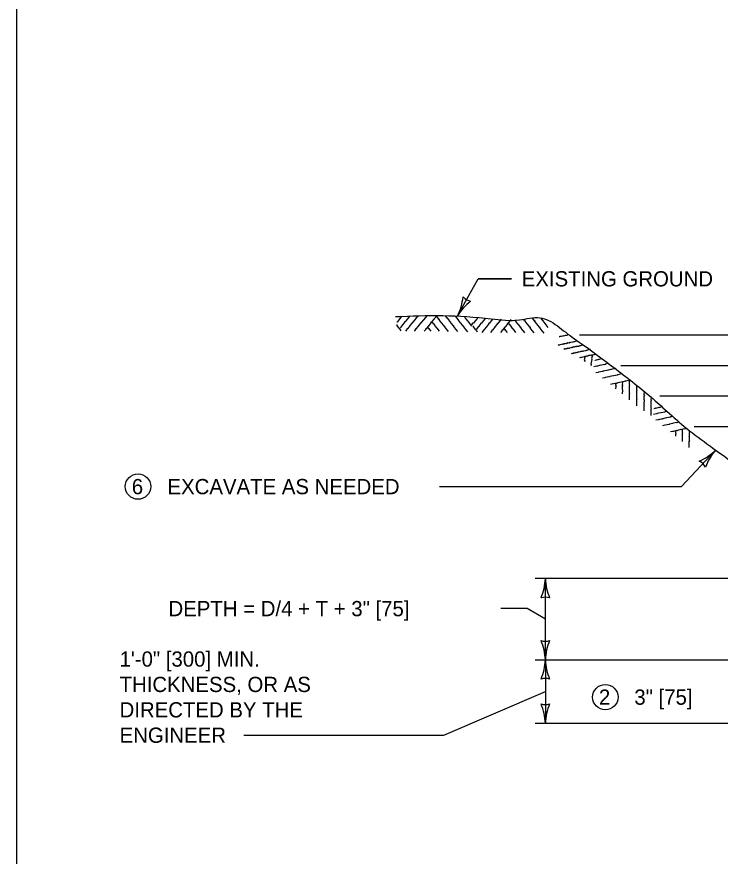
# Model space of a CAD drawing. Extents: x 49991.4 to 50021, y 49987.6 to 50011.4.
# Drawn here: x 49999.384 to 50002.154, y 49992.388 to 49995.693 of the extents above; entities that cross this region are included whole.
import ezdxf

# ---------------------------------------------------------------- set-up
doc = ezdxf.new("R2010")
doc.units = 0
for name, color, linetype in [('Level 1', 7, 'Continuous'), ('Level 2', 7, 'Continuous'), ('Level 3', 7, 'Continuous')]:
    doc.layers.add(name, color=color, linetype=linetype)

msp = doc.modelspace()

# ---------------------------------------------------------------- linework, layer by layer
at = {"layer": 'Level 1'}
for p, q in [((50001.5996, 49994.4405), (50003.795, 49994.4405)), ((50001.7626, 49994.3205), (50003.795, 49994.3205)), ((50001.9159, 49994.2005), (50003.1608, 49994.2005)), ((50002.052, 49994.0805), (50003.0002, 49994.0805))]:
    msp.add_line(p, q, dxfattribs=at)
msp.add_lwpolyline([(49999.3835, 49998.9992), (50016.7501, 49998.9992), (50016.7501, 49987.7988), (49999.3835, 49987.7988)], close=True, dxfattribs=at)
for points in [[(50000.8988, 49994.5131), (50000.8906, 49994.5035), (50000.8914, 49994.5019), (50000.8898, 49994.5019), (50000.8813, 49994.4914), (50000.8802, 49994.4915)], [(50000.932, 49994.5158), (50000.922, 49994.5042), (50000.9228, 49994.5026), (50000.9212, 49994.5026), (50000.9127, 49994.4921), (50000.9106, 49994.4922), (50000.9108, 49994.4901), (50000.902, 49994.4796), (50000.902, 49994.4775), (50000.9001, 49994.4769), (50000.8932, 49994.4682)], [(50000.9648, 49994.517), (50000.9521, 49994.5022), (50000.9529, 49994.5006), (50000.9513, 49994.5006), (50000.9428, 49994.4902), (50000.9406, 49994.4902), (50000.9409, 49994.4882), (50000.9321, 49994.4776), (50000.9321, 49994.4755), (50000.9302, 49994.4749), (50000.9218, 49994.4644), (50000.9198, 49994.4643), (50000.9202, 49994.4623), (50000.9141, 49994.4552)], [(50000.9985, 49994.5164), (50000.9862, 49994.5019), (50000.9869, 49994.5003), (50000.9853, 49994.5004), (50000.9768, 49994.4899), (50000.9747, 49994.4899), (50000.9749, 49994.4879), (50000.9661, 49994.4773), (50000.9661, 49994.4753), (50000.9642, 49994.4746), (50000.9559, 49994.4642), (50000.9539, 49994.464), (50000.9542, 49994.462), (50000.9482, 49994.4549)], [(50001.0388, 49994.5172), (50001.0261, 49994.5024), (50001.0268, 49994.5007), (50001.0252, 49994.5008), (50001.0167, 49994.4903), (50001.0146, 49994.4903), (50001.0148, 49994.4883), (50001.0061, 49994.4777), (50001.006, 49994.4757), (50001.0041, 49994.475), (50000.9958, 49994.4646), (50000.9937, 49994.4645), (50000.9941, 49994.4624), (50000.9881, 49994.4553)], [(50001.0839, 49994.4537), (50001.0786, 49994.461), (50001.0769, 49994.4606), (50001.0773, 49994.4621), (50001.069, 49994.4728), (50001.0695, 49994.4748), (50001.0675, 49994.4751), (50001.0591, 49994.486), (50001.0572, 49994.4865), (50001.057, 49994.4885), (50001.0487, 49994.499), (50001.049, 49994.501), (50001.047, 49994.5011), (50001.0375, 49994.5137)], [(50001.1207, 49994.4538), (50001.1145, 49994.4621), (50001.1128, 49994.4617), (50001.1132, 49994.4633), (50001.1049, 49994.4739), (50001.1054, 49994.476), (50001.1034, 49994.4762), (50001.095, 49994.4872), (50001.0931, 49994.4877), (50001.0929, 49994.4896), (50001.0846, 49994.5002), (50001.0849, 49994.5022), (50001.0829, 49994.5023), (50001.0725, 49994.5161)], [(50001.1596, 49994.4524), (50001.1534, 49994.4607), (50001.1517, 49994.4603), (50001.1521, 49994.4618), (50001.1438, 49994.4725), (50001.1443, 49994.4746), (50001.1423, 49994.4748), (50001.134, 49994.4857), (50001.132, 49994.4862), (50001.1318, 49994.4882), (50001.1235, 49994.4987), (50001.1238, 49994.5007), (50001.1218, 49994.5008), (50001.1126, 49994.5131)], [(50001.1759, 49994.4751), (50001.1681, 49994.4853), (50001.1662, 49994.4858), (50001.166, 49994.4878), (50001.1577, 49994.4983), (50001.158, 49994.5003), (50001.1559, 49994.5004), (50001.1482, 49994.5108)], [(50001.1983, 49994.5066), (50001.1915, 49994.4986), (50001.1923, 49994.497), (50001.1906, 49994.497), (50001.1822, 49994.4865), (50001.181, 49994.4866)], [(50001.2282, 49994.5055), (50001.2229, 49994.4993), (50001.2237, 49994.4977), (50001.2221, 49994.4977), (50001.2136, 49994.4872), (50001.2114, 49994.4873), (50001.2117, 49994.4852), (50001.2029, 49994.4747), (50001.2029, 49994.4726), (50001.201, 49994.472), (50001.1941, 49994.4633)], [(50001.2577, 49994.5028), (50001.253, 49994.4973), (50001.2538, 49994.4957), (50001.2522, 49994.4957), (50001.2437, 49994.4853), (50001.2415, 49994.4853), (50001.2418, 49994.4833), (50001.233, 49994.4727), (50001.233, 49994.4706), (50001.2311, 49994.47), (50001.2227, 49994.4595), (50001.2207, 49994.4594), (50001.221, 49994.4574), (50001.215, 49994.4503)], [(50001.2919, 49994.5027), (50001.287, 49994.497), (50001.2878, 49994.4954), (50001.2862, 49994.4955), (50001.2777, 49994.485), (50001.2756, 49994.485), (50001.2758, 49994.483), (50001.267, 49994.4724), (50001.267, 49994.4704), (50001.2651, 49994.4697), (50001.2568, 49994.4593), (50001.2547, 49994.4592), (50001.2551, 49994.4571), (50001.2491, 49994.45)], [(50001.3299, 49994.5009), (50001.327, 49994.4975), (50001.3277, 49994.4958), (50001.3261, 49994.4959), (50001.3176, 49994.4854), (50001.3155, 49994.4854), (50001.3157, 49994.4834), (50001.3069, 49994.4728), (50001.3069, 49994.4708), (50001.305, 49994.4701), (50001.2967, 49994.4597), (50001.2946, 49994.4596), (50001.295, 49994.4575), (50001.289, 49994.4504)], [(50001.3848, 49994.4488), (50001.3795, 49994.4561), (50001.3778, 49994.4557), (50001.3782, 49994.4572), (50001.3699, 49994.4679), (50001.3704, 49994.47), (50001.3684, 49994.4702), (50001.36, 49994.4811), (50001.3581, 49994.4816), (50001.3579, 49994.4836), (50001.3496, 49994.4941), (50001.3499, 49994.4961), (50001.3478, 49994.4962), (50001.3447, 49994.5004)], [(50001.4215, 49994.4489), (50001.4154, 49994.4572), (50001.4137, 49994.4568), (50001.4141, 49994.4584), (50001.4058, 49994.469), (50001.4063, 49994.4711), (50001.4043, 49994.4713), (50001.3959, 49994.4823), (50001.394, 49994.4828), (50001.3938, 49994.4847), (50001.3855, 49994.4953), (50001.3858, 49994.4973), (50001.3837, 49994.4974), (50001.3812, 49994.5008)], [(50001.4604, 49994.4475), (50001.4543, 49994.4558), (50001.4526, 49994.4554), (50001.453, 49994.4569), (50001.4447, 49994.4676), (50001.4452, 49994.4697), (50001.4432, 49994.4699), (50001.4348, 49994.4808), (50001.4329, 49994.4813), (50001.4327, 49994.4833), (50001.4244, 49994.4938), (50001.4247, 49994.4958), (50001.4227, 49994.4959), (50001.416, 49994.5048)], [(50001.4768, 49994.4702), (50001.469, 49994.4804), (50001.467, 49994.4809), (50001.4669, 49994.4829), (50001.4586, 49994.4934), (50001.4589, 49994.4954), (50001.4568, 49994.4955), (50001.4471, 49994.5085)], [(50000.8978, 49994.4569), (50000.8918, 49994.4651), (50000.89, 49994.4647), (50000.8904, 49994.4662), (50000.8821, 49994.4769), (50000.8827, 49994.479), (50000.8806, 49994.4792), (50000.8801, 49994.4799)], [(50001.0151, 49994.4553), (50001.0092, 49994.4628), (50001.0096, 49994.4648), (50001.0075, 49994.4649), (50001.0018, 49994.4725)], [(50001.0484, 49994.4553), (50001.0389, 49994.4677), (50001.037, 49994.4682), (50001.0368, 49994.4701), (50001.0284, 49994.4807), (50001.0288, 49994.4826), (50001.0267, 49994.4827), (50001.0189, 49994.4932)], [(50001.1787, 49994.4866), (50001.1776, 49994.4866), (50001.1778, 49994.4846), (50001.1746, 49994.4806)], [(50001.1987, 49994.452), (50001.1927, 49994.4602), (50001.1909, 49994.4598), (50001.1913, 49994.4613), (50001.183, 49994.472), (50001.1836, 49994.4741), (50001.1815, 49994.4743), (50001.181, 49994.475)], [(50001.316, 49994.4504), (50001.3101, 49994.4579), (50001.3104, 49994.4599), (50001.3084, 49994.46), (50001.3027, 49994.4676)], [(50001.3493, 49994.4504), (50001.3398, 49994.4628), (50001.3379, 49994.4633), (50001.3376, 49994.4652), (50001.3293, 49994.4758), (50001.3297, 49994.4778), (50001.3276, 49994.4778), (50001.3202, 49994.4878)], [(50001.556, 49994.4424), (50001.5562, 49994.441), (50001.5515, 49994.4398), (50001.5509, 49994.439), (50001.5501, 49994.4396), (50001.5481, 49994.4387), (50001.544, 49994.4383), (50001.5434, 49994.4375), (50001.5427, 49994.4381), (50001.5407, 49994.4372), (50001.5386, 49994.4376), (50001.536, 49994.4359), (50001.5339, 49994.4364), (50001.5332, 49994.4356), (50001.5305, 49994.4353), (50001.5299, 49994.4346), (50001.5291, 49994.4352), (50001.5272, 49994.4342), (50001.5264, 49994.4348), (50001.5258, 49994.4341), (50001.5231, 49994.4338), (50001.5224, 49994.433), (50001.5217, 49994.4336), (50001.5197, 49994.4327)], [(50001.5885, 49994.4191), (50001.5888, 49994.4164), (50001.5794, 49994.4139), (50001.5782, 49994.4124), (50001.5767, 49994.4136), (50001.5727, 49994.4118), (50001.5645, 49994.4108), (50001.5633, 49994.4093), (50001.5618, 49994.4105), (50001.5579, 49994.4087), (50001.5536, 49994.4095), (50001.5484, 49994.4062), (50001.5441, 49994.4071), (50001.5429, 49994.4056), (50001.5375, 49994.4049), (50001.5363, 49994.4034), (50001.5347, 49994.4046), (50001.5308, 49994.4028), (50001.5293, 49994.404), (50001.5281, 49994.4024), (50001.5226, 49994.4018), (50001.5214, 49994.4003), (50001.5199, 49994.4015), (50001.5159, 49994.3996)], [(50001.6112, 49994.403), (50001.6115, 49994.4003), (50001.602, 49994.3978), (50001.6008, 49994.3963), (50001.5993, 49994.3975), (50001.5954, 49994.3956), (50001.5872, 49994.3947), (50001.5859, 49994.3932), (50001.5844, 49994.3944), (50001.5805, 49994.3926), (50001.5762, 49994.3935), (50001.571, 49994.39), (50001.5668, 49994.391), (50001.5656, 49994.3894), (50001.5601, 49994.3888), (50001.5589, 49994.3873), (50001.5574, 49994.3885), (50001.5534, 49994.3866), (50001.5519, 49994.3879), (50001.5507, 49994.3864), (50001.5452, 49994.3857), (50001.544, 49994.3842), (50001.5425, 49994.3854), (50001.5386, 49994.3835)], [(50001.6158, 49994.4001), (50001.63, 49994.3913), (50001.6699, 49994.3606)], [(50001.6402, 49994.3856), (50001.6405, 49994.3828), (50001.6311, 49994.3804), (50001.6299, 49994.3789), (50001.6284, 49994.3801), (50001.6244, 49994.3782), (50001.6162, 49994.3773), (50001.615, 49994.3757), (50001.6135, 49994.3769), (50001.6095, 49994.3751), (50001.6053, 49994.376), (50001.6001, 49994.3726), (50001.5959, 49994.3735), (50001.5946, 49994.372), (50001.5891, 49994.3713), (50001.588, 49994.3699), (50001.5864, 49994.3711), (50001.5825, 49994.3692), (50001.5809, 49994.3705), (50001.5797, 49994.3689), (50001.5743, 49994.3683), (50001.5731, 49994.3667), (50001.5715, 49994.3679), (50001.5676, 49994.3661)], [(50001.6644, 49994.3647), (50001.6644, 49994.3647), (50001.6631, 49994.3643), (50001.6619, 49994.3628), (50001.6603, 49994.364), (50001.6564, 49994.3621), (50001.6482, 49994.3612), (50001.647, 49994.3596), (50001.6455, 49994.3609), (50001.6415, 49994.359), (50001.6372, 49994.3599), (50001.6321, 49994.3566), (50001.6279, 49994.3575), (50001.6267, 49994.3559), (50001.6211, 49994.3553), (50001.6199, 49994.3538), (50001.6184, 49994.355), (50001.6145, 49994.3532), (50001.613, 49994.3544), (50001.6117, 49994.3528), (50001.6063, 49994.3522), (50001.605, 49994.3507), (50001.6035, 49994.3519), (50001.5996, 49994.35)], [(50001.6228, 49994.3565), (50001.6188, 49994.3422), (50001.6207, 49994.3383), (50001.62, 49994.3349)], [(50001.6505, 49994.3618), (50001.6467, 49994.3475), (50001.6485, 49994.3435), (50001.6449, 49994.3265), (50001.6465, 49994.3253), (50001.6455, 49994.321), (50001.6445, 49994.3197)], [(50001.6884, 49994.3464), (50001.676, 49994.3439), (50001.6757, 49994.3422), (50001.6744, 49994.3432), (50001.6612, 49994.3402), (50001.6604, 49994.341)], [(50001.7161, 49994.3278), (50001.7011, 49994.325), (50001.7007, 49994.3232), (50001.6995, 49994.3242), (50001.6863, 49994.3213), (50001.6847, 49994.3227), (50001.6835, 49994.3209), (50001.6701, 49994.3181), (50001.6688, 49994.3165), (50001.667, 49994.3172), (50001.6561, 49994.3147)], [(50001.7426, 49994.3084), (50001.7234, 49994.3047), (50001.7231, 49994.3029), (50001.7218, 49994.3039), (50001.7087, 49994.3011), (50001.707, 49994.3024), (50001.7059, 49994.3007), (50001.6925, 49994.2979), (50001.6912, 49994.2962), (50001.6893, 49994.2969), (50001.6762, 49994.2939), (50001.6746, 49994.2951), (50001.6736, 49994.2933), (50001.6644, 49994.2915)], [(50001.7686, 49994.287), (50001.7499, 49994.2833), (50001.7495, 49994.2816), (50001.7483, 49994.2826), (50001.7351, 49994.2797), (50001.7335, 49994.281), (50001.7324, 49994.2793), (50001.7189, 49994.2765), (50001.7177, 49994.2749), (50001.7157, 49994.2756), (50001.7028, 49994.2726), (50001.7011, 49994.2736), (50001.7001, 49994.2719), (50001.691, 49994.2701)], [(50001.8007, 49994.2626), (50001.7815, 49994.2589), (50001.781, 49994.2571), (50001.7798, 49994.2582), (50001.7666, 49994.2552), (50001.765, 49994.2565), (50001.7639, 49994.2548), (50001.7505, 49994.2519), (50001.7492, 49994.2504), (50001.7472, 49994.2511), (50001.7343, 49994.2481), (50001.7326, 49994.2493), (50001.7316, 49994.2474), (50001.7225, 49994.2456)], [(50001.7436, 49994.2288), (50001.7437, 49994.2383), (50001.7452, 49994.2397), (50001.7436, 49994.241), (50001.7439, 49994.2505)], [(50001.7697, 49994.2081), (50001.77, 49994.2237), (50001.7688, 49994.2253), (50001.7698, 49994.2269), (50001.7698, 49994.2404), (50001.7713, 49994.2417), (50001.7697, 49994.2431), (50001.7702, 49994.2561)], [(50001.7965, 49994.1848), (50001.7969, 49994.1938), (50001.7953, 49994.1945), (50001.7966, 49994.1955), (50001.7967, 49994.209), (50001.7984, 49994.2103), (50001.797, 49994.2117), (50001.7972, 49994.2255), (50001.796, 49994.2271), (50001.7971, 49994.2288), (50001.7971, 49994.2421), (50001.7986, 49994.2435), (50001.7971, 49994.2448), (50001.7975, 49994.2606)], [(50001.8254, 49994.162), (50001.8257, 49994.1723), (50001.8241, 49994.1731), (50001.8254, 49994.1741), (50001.8255, 49994.1876), (50001.8272, 49994.1889), (50001.8258, 49994.1903), (50001.826, 49994.2041), (50001.8249, 49994.2057), (50001.8259, 49994.2073), (50001.826, 49994.2208), (50001.8275, 49994.2222), (50001.8259, 49994.2235), (50001.8264, 49994.2407)], [(50001.8547, 49994.1414), (50001.855, 49994.1518), (50001.8534, 49994.1525), (50001.8546, 49994.1535), (50001.8548, 49994.167), (50001.8565, 49994.1683), (50001.855, 49994.1697), (50001.8553, 49994.1834), (50001.8541, 49994.1851), (50001.8552, 49994.1868), (50001.8552, 49994.2001), (50001.8567, 49994.2015), (50001.8551, 49994.2028), (50001.8556, 49994.2182)], [(50001.8825, 49994.152), (50001.8827, 49994.1648), (50001.8815, 49994.1664), (50001.8826, 49994.1681), (50001.8826, 49994.1814), (50001.8841, 49994.1828), (50001.8825, 49994.1842), (50001.883, 49994.1971)], [(50001.8817, 49994.1234), (50001.8821, 49994.1336), (50001.8805, 49994.1344), (50001.8817, 49994.1353), (50001.8819, 49994.1488), (50001.8837, 49994.1501), (50001.8821, 49994.1516), (50001.8822, 49994.1524)], [(50001.9447, 49994.1394), (50001.9367, 49994.1378), (50001.9363, 49994.1361), (50001.9351, 49994.1371), (50001.9219, 49994.1341), (50001.9202, 49994.1356), (50001.9192, 49994.1337), (50001.9057, 49994.131), (50001.9044, 49994.1293), (50001.9026, 49994.13), (50001.8918, 49994.1275)], [(50001.8992, 49994.1519), (50001.8983, 49994.1526), (50001.8972, 49994.1509), (50001.8923, 49994.1497)], [(50001.925, 49994.157), (50001.9147, 49994.1549), (50001.9144, 49994.1532), (50001.913, 49994.1542), (50001.8999, 49994.1512), (50001.899, 49994.152)], [(50001.9661, 49994.1189), (50001.959, 49994.1175), (50001.9587, 49994.1158), (50001.9574, 49994.1168), (50001.9443, 49994.1139), (50001.9426, 49994.1153), (50001.9416, 49994.1135), (50001.9281, 49994.1107), (50001.9268, 49994.1091), (50001.9249, 49994.1098), (50001.9118, 49994.1068), (50001.9102, 49994.1079), (50001.9092, 49994.1062), (50001.9001, 49994.1043)], [(50001.9929, 49994.0976), (50001.9855, 49994.0962), (50001.9851, 49994.0944), (50001.9839, 49994.0955), (50001.9707, 49994.0926), (50001.9691, 49994.0939), (50001.968, 49994.0922), (50001.9545, 49994.0893), (50001.9533, 49994.0878), (50001.9514, 49994.0884), (50001.9384, 49994.0854), (50001.9367, 49994.0866), (50001.9357, 49994.0847), (50001.9266, 49994.0829)], [(50002.0215, 49994.0726), (50002.0171, 49994.0717), (50002.0166, 49994.0699), (50002.0154, 49994.071), (50002.0022, 49994.0681), (50002.0006, 49994.0694), (50001.9995, 49994.0677), (50001.986, 49994.0649), (50001.9848, 49994.0633), (50001.9829, 49994.0639), (50001.9699, 49994.0609), (50001.9682, 49994.0622), (50001.9672, 49994.0603), (50001.9581, 49994.0584)], [(50001.9792, 49994.0416), (50001.9793, 49994.0512), (50001.9808, 49994.0526), (50001.9793, 49994.0539), (50001.9795, 49994.0634)], [(50002.0053, 49994.021), (50002.0056, 49994.0366), (50002.0044, 49994.0381), (50002.0054, 49994.0398), (50002.0054, 49994.0533), (50002.007, 49994.0546), (50002.0054, 49994.0559), (50002.0058, 49994.0683)], [(50002.0321, 49993.9976), (50002.0325, 49994.0066), (50002.0309, 49994.0074), (50002.0322, 49994.0083), (50002.0323, 49994.0219), (50002.034, 49994.0232), (50002.0326, 49994.0246), (50002.0328, 49994.0384), (50002.0316, 49994.0399), (50002.0327, 49994.0416), (50002.0327, 49994.055), (50002.0342, 49994.0564), (50002.0326, 49994.0578), (50002.0328, 49994.063)]]:
    msp.add_lwpolyline(points, dxfattribs=at)
for points in [[(50000.8754, 49994.5126), (50001.0615, 49994.5168), (50001.2518, 49994.5042), (50001.3639, 49994.4999), (50001.4443, 49994.5084), (50001.4782, 49994.4978), (50001.5455, 49994.4509), (50001.6158, 49994.4001)], [(50001.6699, 49994.3606), (50001.8183, 49994.2482), (50001.9442, 49994.1403), (50002.0221, 49994.0723), (50002.113, 49994.0037), (50002.1153, 49994.0019)], [(50002.1153, 49994.0019), (50002.2637, 49993.8895), (50002.2721, 49993.8822)]]:
    msp.add_spline(points, degree=3, dxfattribs=at)
at = {"layer": 'Level 2'}
for centre in [(49999.861, 49993.8433), (50001.7017, 49993.0143)]:
    msp.add_circle(centre, 0.05, dxfattribs=at)
at = {"layer": 'Level 3'}
for p, q in [((50001.1192, 49994.5154), (50001.2003, 49994.6616)), ((50001.3325, 49994.6616), (50001.2003, 49994.6616)), ((50001.2003, 49994.6616), (50001.3325, 49994.6616)), ((50002.136, 49993.9872), (50002.0012, 49993.8433)), ((50001.0483, 49993.8433), (50002.0012, 49993.8433)), ((50002.3196, 49993.4813), (50001.4254, 49993.4813)), ((50001.4654, 49993.1612), (50001.4654, 49993.4813)), ((50001.3944, 49993.3628), (50001.2905, 49993.3628)), ((50001.4654, 49993.3213), (50001.3944, 49993.3628)), ((50001.4254, 49993.1612), (50002.3196, 49993.1612)), ((50001.4654, 49993.1612), (50001.4654, 49992.9112)), ((50001.0655, 49992.8643), (50001.4654, 49993.0362)), ((50001.4254, 49992.9112), (50002.3196, 49992.9112)), ((50000.2783, 49992.8643), (50001.0655, 49992.8643))]:
    msp.add_line(p, q, dxfattribs=at)
for centre, radius, start, end in [((50000.9206, 49994.6151), 0.2223, 333.3425, 353.526), ((50001.3172, 49994.3924), 0.233, 128.9048, 148.1547), ((50001.1814, 49994.6275), 0.0548, 223.1208, 258.8432), ((50001.9802, 49994.1458), 0.2223, 294.3067, 314.4902), ((50002.3137, 49993.8365), 0.233, 139.678, 158.9279), ((50002.0484, 49993.8937), 0.0548, 28.9895, 64.7119), ((50001.2433, 49993.4905), 0.2223, 337.456, 357.6395), ((50001.6981, 49993.4928), 0.233, 182.8273, 202.0772), ((50001.4654, 49993.3531), 0.0548, 72.1388, 107.8612), ((50001.4654, 49993.2894), 0.0548, 252.1388, 287.8612), ((50001.2327, 49993.1497), 0.233, 2.8273, 22.0772), ((50001.6875, 49993.152), 0.2223, 157.456, 177.6395), ((50001.2433, 49993.1703), 0.2223, 337.456, 357.6395), ((50001.6981, 49993.1727), 0.233, 182.8273, 202.0772), ((50001.4654, 49993.033), 0.0548, 72.1388, 107.8612), ((50001.4654, 49993.0394), 0.0548, 252.1388, 287.8612), ((50001.2327, 49992.8997), 0.233, 2.8273, 22.0772), ((50001.6875, 49992.902), 0.2223, 157.456, 177.6395)]:
    msp.add_arc(centre, radius, start, end, dxfattribs=at)

# ---------------------------------------------------------------- texts
at = {"layer": 'Level 2'}
for s, p in [('EXISTING GROUND', (50001.3725, 49994.6316)), ('6', (49999.8365, 49993.8133)), ('EXCAVATE AS NEEDED', (49999.9771, 49993.8133)), ('DEPTH = D/4 + T + 3" [75]', (49999.981, 49993.3328)), ('1\'-0" [300] MIN.', (49999.7884, 49993.1343)), ('THICKNESS, OR AS ', (49999.7884, 49993.0343)), ('2', (50001.6765, 49992.9843)), ('3" [75]', (50001.8159, 49992.9843)), ('DIRECTED BY THE', (49999.7884, 49992.9343)), ('ENGINEER', (49999.7884, 49992.8343))]:
    msp.add_text(s, height=0.06, dxfattribs=at).set_placement(p)

doc.saveas('drawing.dxf')
